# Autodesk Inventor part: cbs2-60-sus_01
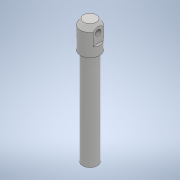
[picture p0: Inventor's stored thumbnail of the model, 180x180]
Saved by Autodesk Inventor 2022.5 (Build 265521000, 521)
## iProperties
Part Number: cbs2-60-sus_01
Material: 一般
Document SubType Name: Modeling
Designer: ImaoCorp
Density: 1 g/cm^3
Appearance: 既定
Author: ImaoCorp
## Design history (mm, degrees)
feature "cbs2-60-sus_01"
node "ソリッド1"
